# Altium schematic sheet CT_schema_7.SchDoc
size 274 x 160 mm
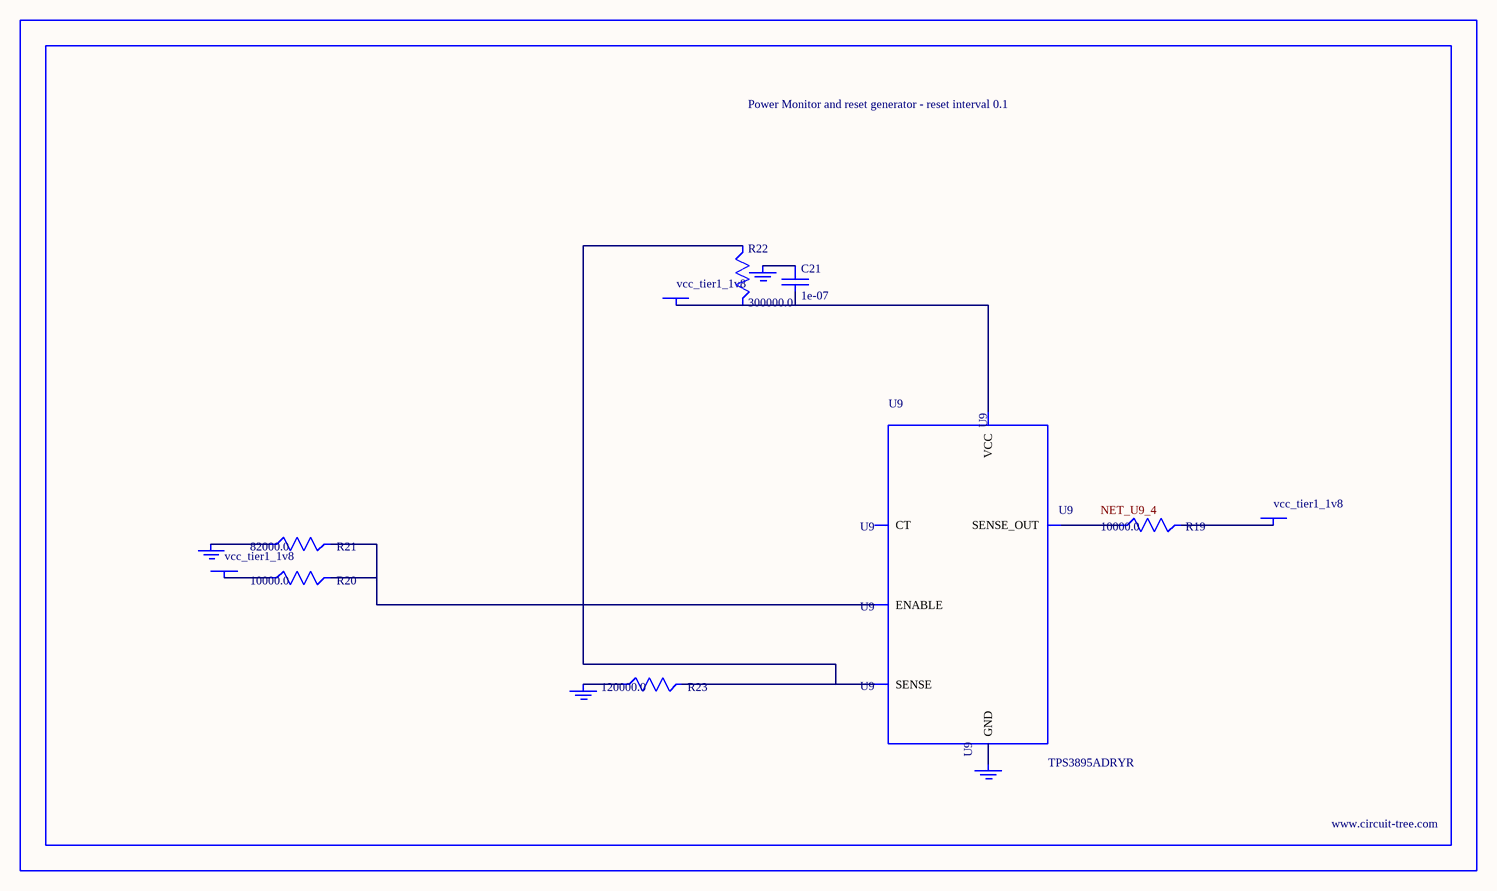
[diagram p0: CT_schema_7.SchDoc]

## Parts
BORDER6  (no value)
C21  1e-07  [C0402]
GND_INSTANCE_6_0  (no value)
GND_INSTANCE_6_1  (no value)
GND_INSTANCE_6_2  (no value)
GND_INSTANCE_6_3  (no value)
POWER_INSTANCE_6_0  vcc_tier1_1v8
POWER_INSTANCE_6_1  vcc_tier1_1v8
POWER_INSTANCE_6_2  vcc_tier1_1v8
R19  10000.0  [R0603]
R20  10000.0  [R0603]
R21  82000.0  [R0603]
R22  300000.0  [R0603]
R23  120000.0  [R0603]
U9  TPS3895ADRYR  [SON-6]

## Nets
NetC21_1: C21.1 GND_INSTANCE_6_2.0(GND)
NetC21_2: C21.2 POWER_INSTANCE_6_2.0(PWR) R22.2 U9.6(VCC)
NetGND_INSTANCE_6_0_0: GND_INSTANCE_6_0.0(GND) R21.1
NetGND_INSTANCE_6_1_0: GND_INSTANCE_6_1.0(GND) R23.1
NetGND_INSTANCE_6_3_0: GND_INSTANCE_6_3.0(GND) U9.2(GND)
NetPOWER_INSTANCE_6_0_0: POWER_INSTANCE_6_0.0(PWR) R20.1
NetPOWER_INSTANCE_6_1_0: POWER_INSTANCE_6_1.0(PWR) R19.2
NetR19_1: R19.1 U9.4(SENSE_OUT)
NetR20_2: R20.2 R21.2 U9.1(ENABLE)
NetR22_1: R22.1 R23.2 U9.3(SENSE)

Not connected (* = marked no-connect by the designer): U9 5(CT)

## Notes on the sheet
- Labels drawn without touching a wire or pin: NET_U9_4

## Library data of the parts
BORDER6 = BORDER_PAGE6
C21 = C0402C104K3RACTU
GND_INSTANCE_6_0-GND_INSTANCE_6_3 = GND
POWER_INSTANCE_6_0-POWER_INSTANCE_6_2 = PWR
R19 R20 = RC0603JR-0710KL
R21 = RC0603JR-0782KL
R22 = RC0603JR-07300KL
R23 = RC0603JR-07120KL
